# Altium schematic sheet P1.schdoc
size 297 x 209 mm; Symbol: Drawing-Symbol_A4; Company: 嘉立创EDA; Version: V1.0; Page Size: A4; @Project Name: 手机遥控开关; @Update Date: 2026-04-07; @Create Date: 2026-04-07; Device: Drawing-Symbol_A4; @Board Name: Board1; @Page Name: P1; @Create Time: 19:07:08; @Page Count: 1; @Page No: 1; @Schematic Name: Schematic1; @Update Time: 19:07:08; @Assembly Variant: Basic; Border: 1; Title Block Position: 3; Size: A4; Width: 1170; Height: 825; Region Start: 1; X Region Count: 6; Y Region Count: 4; Blade Width: 10
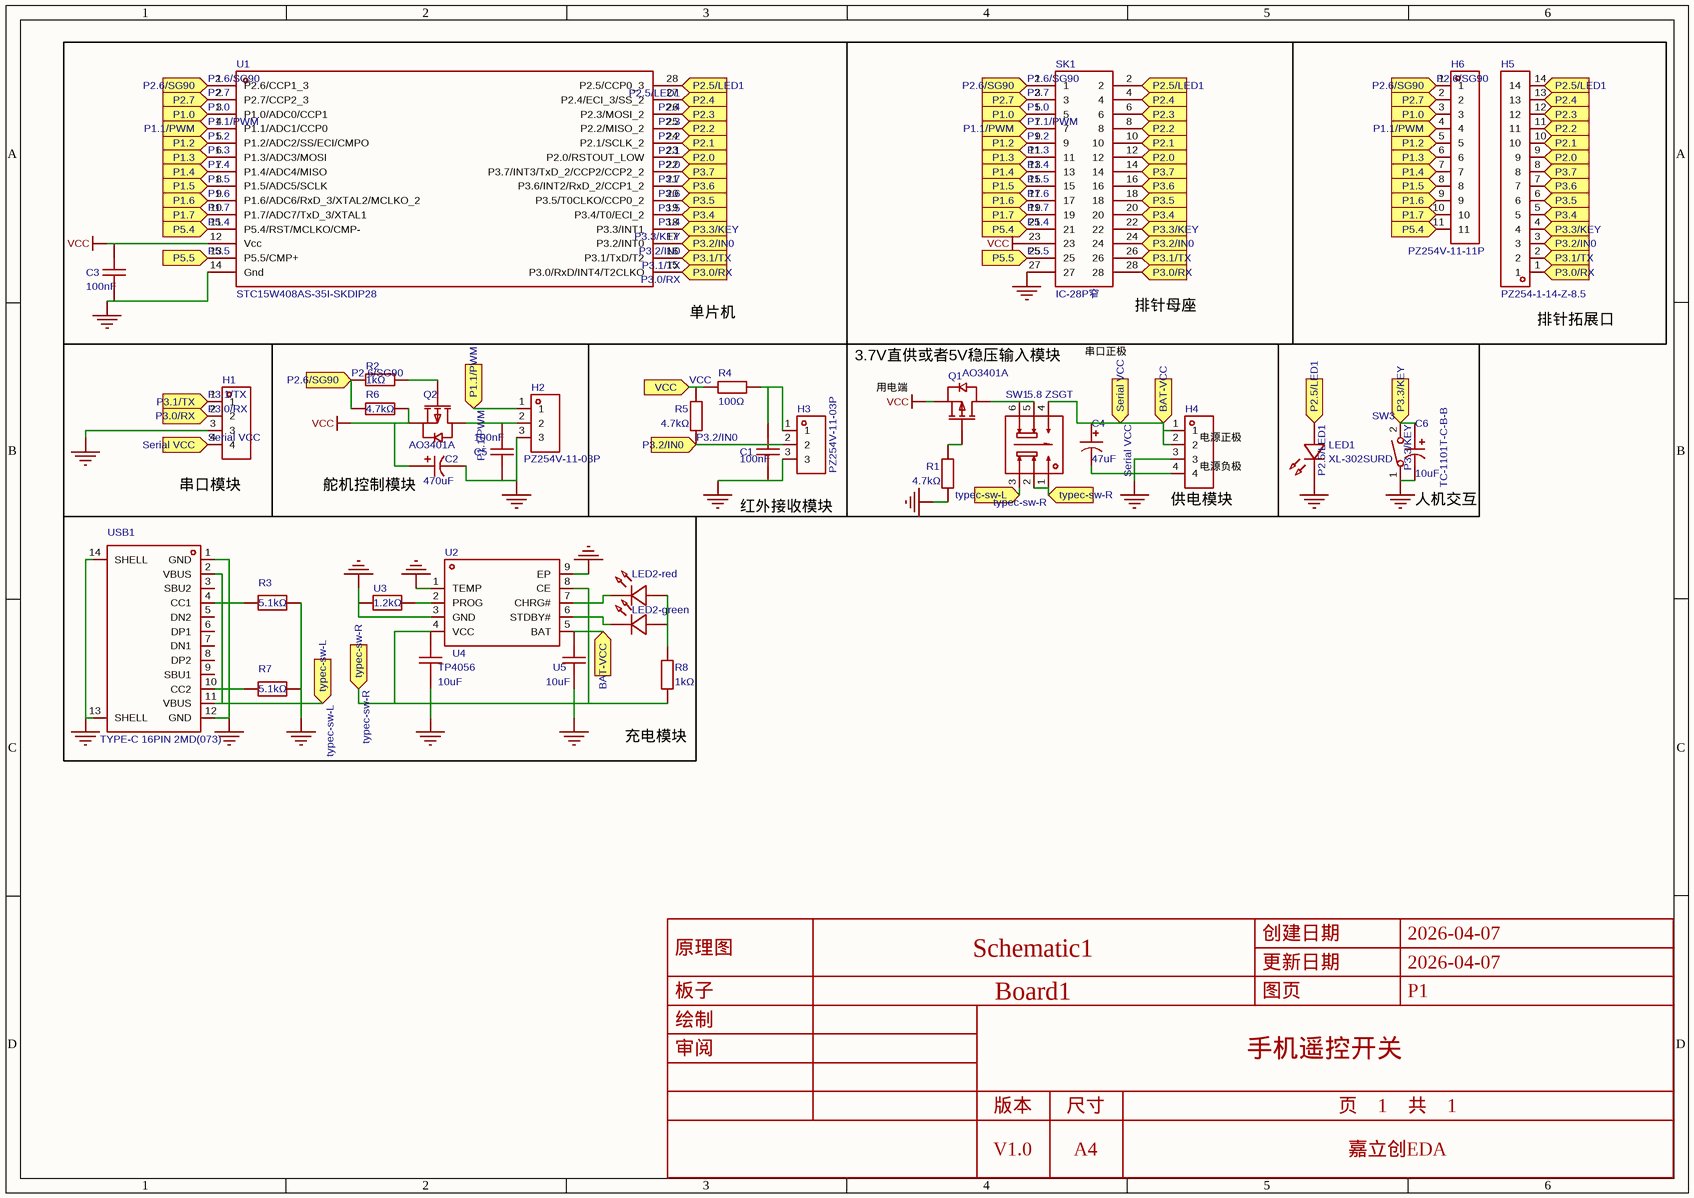
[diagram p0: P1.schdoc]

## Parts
C1  100nF  [CAP-TH_L5.0-W2.5-P5.00-D1.0]
C2  470uF  [CAP-TH_BD8.0-P3.50-D0.6-FD_1]
C3  100nF  [CAP-TH_L5.0-W2.5-P5.00-D1.0]
C4  47uF  [CAP-TH_BD6.3-P2.50-D1.0-FD]
C5  100nF  [CAP-TH_L5.0-W2.5-P5.00-D1.0]
C6  10uF  [CAP-TH_BD5.0-P2.00-D0.5-FD-A]
H1  (no value)  [HDR-TH_4P-P2.54-V-M]
H2  PZ254V-11-03P  [HDR-TH_3P-P2.54-V-M_PZ254V-11-03P]
H3  PZ254V-11-03P  [HDR-TH_3P-P2.54-V-M_PZ254V-11-03P]
H4  (no value)  [HDR-TH_4P-P2.54-V-M]
H5  PZ254-1-14-Z-8.5  [HDR-TH_14P-P2.54-V-M]
H6  PZ254V-11-11P  [HDR-TH_11P-P2.54-V-M]
LED1  XL-302SURD  [LED-TH_BD3.8-P2.54-RD]
LED2-green  (no value)  [LED-TH_BD3.8-P2.54-FD_GREEN]
LED2-red  (no value)  [LED-TH_BD3.8-P2.54-RD]
Q1  AO3401A  [SOT-23_L2.9-W1.3-P1.90-LS2.4-BR]
Q2  AO3401A  [SOT-23_L2.9-W1.3-P1.90-LS2.4-BR]
R1  4.7kΩ  [RES-TH_BD2.3-L6.5-P10.50-D0.5]
R2  1kΩ  [RES-TH_BD2.5-L6.5-P10.50-D0.6]
R3  5.1kΩ  [RES-TH_BD2.3-L6.5-P10.50-D0.5]
R4  100Ω  [RES-TH_BD2.2-L6.5-P10.50-D0.6]
R5  4.7kΩ  [RES-TH_BD2.3-L6.5-P10.50-D0.5]
R6  4.7kΩ  [RES-TH_BD2.3-L6.5-P10.50-D0.5]
R7  5.1kΩ  [RES-TH_BD2.3-L6.5-P10.50-D0.5]
R8  1kΩ  [RES-TH_BD2.5-L6.5-P10.50-D0.6]
SK1  IC-28P窄  [DIP-28_L36.0-W10.2-P2.54-LS10.2-BL]
SW1  5.8 ZSGT  [SW-TH_5.8ZSGT]
SW3  TC-1101T-C-B-B  [KEY-TH_2P-L6.0-W3.5-P6.50]
U1  STC15W408AS-35I-SKDIP28  [DIP-28_L35.0-W6.5-P2.54-LS7.6-BL]
U2  TP4056  [ESOP-8_L4.9-W3.9-P1.27-LS6.0-BL-EP]
U3  1.2kΩ  [RES-TH_BD2.4-L6.3-P10.30-D0.6]
U4  10uF  [CAP-TH_L5.5-W3.8-P5.08-D0.5]
U5  10uF  [CAP-TH_L5.5-W3.8-P5.08-D0.5]
USB1  TYPE-C 16PIN 2MD(073)  [USB-C-SMD_TYPE-C-6PIN-2MD-073]

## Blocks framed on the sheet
单片机: C3 U1
排针母座: SK1
排针拓展口: H5 H6
串口模块: H1
舵机控制模块: C2 C5 H2 Q2 R2 R6
红外接收模块: C1 H3 R4 R5
人机交互: C6 LED1 SW3
充电模块: LED2-green LED2-red R3 R7 R8 U2-U5 USB1

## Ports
BAT-VCC (in), P1.0 (in), P1.1/PWM (in), P1.2 (in), P1.3 (in), P1.4 (in), P1.5 (in), P1.6 (in), P1.7 (in), P2.0 (in), P2.1 (in), P2.2 (in), P2.3 (in), P2.4 (in), P2.5/LED1 (in), P2.6/SG90 (in), P2.7 (in), P3.0/RX (in), P3.1/TX (in), P3.2/IN0 (in), P3.3/KEY (in), P3.4 (in), P3.5 (in), P3.6 (in), P3.7 (in), P5.4 (in), P5.5 (in), Serial VCC (in), typec-sw-L (in), typec-sw-R (in), VCC (in)

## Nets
GND: C1.1 C2.2 C3.1 C4.2 C5.1 C6.2 H1.3 H2.3 H3.3 H4.3 H4.4 LED1.1(K) R1.1 R3.1 R3.2 R7.1 R7.2 SK1.27 SW3.1 U1.14(Gnd) U2.1(TEMP) U2.3(GND) U2.9(EP) U3.1 U4.1 U5.1 USB1.1(GND) USB1.4(CC1) USB1.10(CC2) USB1.12(GND) USB1.13(SHELL) USB1.14(SHELL)
VCC: C2.1 C3.2 Q1.2(S) Q2.2(S) R4.1 R5.2 R6.2 SK1.23 U1.12(Vcc) ; port VCC
P1.0: H6.3 SK1.5 U1.3(P1.0/ADC0/CCP1) ; port P1.0
P1.1/PWM: H2.1 H6.4 SK1.7 U1.4(P1.1/ADC1/CCP0) ; port P1.1/PWM
P1.2: H6.5 SK1.9 U1.5(P1.2/ADC2/SS/ECI/CMPO) ; port P1.2
P1.3: H6.6 SK1.11 U1.6(P1.3/ADC3/MOSI) ; port P1.3
P1.4: H6.7 SK1.13 U1.7(P1.4/ADC4/MISO) ; port P1.4
P1.5: H6.8 SK1.15 U1.8(P1.5/ADC5/SCLK) ; port P1.5
P1.6: H6.9 SK1.17 U1.9(P1.6/ADC6/RxD_3/XTAL2/MCLKO_2) ; port P1.6
P1.7: H6.10 SK1.19 U1.10(P1.7/ADC7/TxD_3/XTAL1) ; port P1.7
P2.0: H5.9 SK1.12 U1.23(P2.0/RSTOUT_LOW) ; port P2.0
P2.1: H5.10 SK1.10 U1.24(P2.1/SCLK_2) ; port P2.1
P2.2: H5.11 SK1.8 U1.25(P2.2/MISO_2) ; port P2.2
P2.3: H5.12 SK1.6 U1.26(P2.3/MOSI_2) ; port P2.3
P2.4: H5.13 SK1.4 U1.27(P2.4/ECI_3/SS_2) ; port P2.4
P2.5/LED1: H5.14 LED1.2(A) SK1.2 U1.28(P2.5/CCP0_3) ; port P2.5/LED1
P2.6/SG90: H6.1 R2.1 R6.1 SK1.1 U1.1(P2.6/CCP1_3) ; port P2.6/SG90
P2.7: H6.2 SK1.3 U1.2(P2.7/CCP2_3) ; port P2.7
P3.0/RX: H1.2 H5.1 SK1.28 U1.15(P3.0/RxD/INT4/T2CLKO) ; port P3.0/RX
P3.1/TX: H1.1 H5.2 SK1.26 U1.16(P3.1/TxD/T2) ; port P3.1/TX
P3.2/IN0: H3.2 H5.3 R5.1 SK1.24 U1.17(P3.2/INT0) ; port P3.2/IN0
P3.3/KEY: C6.1 H5.4 SK1.22 SW3.2 U1.18(P3.3/INT1) ; port P3.3/KEY
P3.4: H5.5 SK1.20 U1.19(P3.4/T0/ECI_2) ; port P3.4
P3.5: H5.6 SK1.18 U1.20(P3.5/T0CLKO/CCP0_2) ; port P3.5
P3.6: H5.7 SK1.16 U1.21(P3.6/INT2/RxD_2/CCP1_2) ; port P3.6
P3.7: H5.8 SK1.14 U1.22(P3.7/INT3/TxD_2/CCP2/CCP2_2) ; port P3.7
P5.4: H6.11 SK1.21 U1.11(P5.4/RST/MCLKO/CMP-) ; port P5.4
P5.5: SK1.25 U1.13(P5.5/CMP+) ; port P5.5
Serial VCC: C4.1 H1.4 H4.1 H4.2 SW1.4 U2.5(BAT) U5.2 ; port Serial VCC, port BAT-VCC
typec-sw-L: SW1.3 USB1.2(VBUS) USB1.11(VBUS) ; port typec-sw-L
typec-sw-R: R8.2 SW1.1 SW1.2 U2.4(VCC) U2.8(CE) U4.2 ; port typec-sw-R
NetC1_2: C1.2 H3.1 R4.2
NetC5_2: C5.2 H2.2 Q2.3(D)
NetLED2-green_1: LED2-green.1(A) LED2-red.2(A) R8.1
NetLED2-green_2: LED2-green.2(K) U2.6(STDBY#)
NetLED2-red_1: LED2-red.1(K) U2.7(CHRG#)
NetQ1_1: Q1.1(G) R1.2
NetQ1_3: Q1.3(D) SW1.5 SW1.6
NetQ2_1: Q2.1(G) R2.2
NetU2_2: U2.2(PROG) U3.2

Not connected (* = marked no-connect by the designer): USB1 3(SBU2) 5(DN2) 6(DP1) 7(DN1) 8(DP2) 9(SBU1)

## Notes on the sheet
- (near Q1) 3.7V直供或者5V稳压输入模块
- 串口正极
- 用电端
- (near H4) 供电模块
- (near H4) 电源正极
- (near H4) 电源负极

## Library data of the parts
C1 = CC1H104MC1FD3F6C10MF: 容值:100nF;精度:±20%;额定电压:50V;温度系数:Y5V;; Manufacturer: Dersonic(德尔创); AddInBom: yes; ModelId: 08e3d7481fc7486bb1b263873f51e1e10819f05c4eef4c71ace90d822a990e87; ModelName: CAP-TH_BD5.0-W2.5-P5.08; ModelTransform: 224.652,98.425,0,0,0,0,-0.005,0,-137.795; Tolerance: ±20%; Voltage Rating: 50V; Pin Spacing: 5.08mm; Temperature Coefficient: Y5V; Body Thickness: 2.2mm
C2 = CD2884771EM0812VFL: 容值:470uF;精度:±20%;额定电压:25V;纹波电流:905mA@100kHz;等效串联电阻(ESR):69mΩ@100kHz;; Manufacturer: HRK(鸿瑞凯电子); AddInBom: yes; ModelId: 5fc21599cab34df2ad7753b19b2f52860819f05c4eef4c71ace90d822a990e87; ModelTransform: 315.365,314.914,0,0,0,0,0,0,-196.85; Tolerance: ±20%; Voltage Rating: 25V; Pin Spacing: 3.5mm; Lifetime: 3000hrs@105℃
C3 C5 = CC1H104MC1FD3F6C10MF: 容值:100nF;精度:±20%;额定电压:50V;温度系数:Y5V;; Manufacturer: Dersonic(德尔创); 3D Model: 08e3d7481fc7486bb1b263873f51e1e10819f05c4eef4c71ace90d822a990e87; 3D Model Transform: 224.652,98.425,0,0,0,0,-0.005,0,-137.795; Tolerance: ±20%; Voltage Rating: 50V; Pin Spacing: 5.08mm; Temperature Coefficient: Y5V; Body Thickness: 2.2mm; AddInBom: yes; ModelName: CAP-TH_BD5.0-W2.5-P5.08
C4 = ERS1HM470E110T: 容值:47uF;精度:±20%;额定电压:50V;; Manufacturer: AISHI(艾华集团); AddInBom: yes; ModelId: 0a4db4bf24b443b3be4905be97ff10c50819f05c4eef4c71ace90d822a990e87; ModelTransform: 248.4247,247.99777,0,0,0,0,0,0,-137.795; Tolerance: ±20%; Voltage Rating: 50V; Pin Spacing: 2.5mm; Lifetime: 5000hrs@105℃
C6 = ERG50V10M5X11: 容值:10uF;精度:±20%;额定电压:50V;纹波电流:180mA@100kHz;等效串联电阻(ESR):1.3Ω@100kHz;; Manufacturer: JIERR(捷而瑞); AddInBom: yes; ModelId: 230b3bd6484f4b52b9cf74c8bd6c61990819f05c4eef4c71ace90d822a990e87; ModelTransform: 197.2437,197.23953,0,0,0,0,0,0,-196.85; Tolerance: ±20%; Voltage Rating: 50V; Pin Spacing: 2mm; Lifetime: 2000hrs@105℃
H1 H4 = PZ254V-11-04P: 插针结构:1x4P;间距:2.54mm;行距:-;圆针/方针:方针;安装方式:直插;排数:单排;总PIN位数:4P;额定电流:3A;额定电压:250V;配合针长度:6mm;塑高:2.5mm;端接针长度:3mm;触头材质:-;工作温度:-40℃~+105℃;颜色:黑色;; Manufacturer: XFCN(兴飞); Symbol: PZ254V-11-04P_C2691448; AddInBom: yes; ModelId: 112f4d05e8d64e99ab9a333894bea4f90819f05c4eef4c71ace90d822a990e87; ModelName: HDR-TH_4P-P2.54-M-LI-1X4P; ModelTransform: 399.999,104.7242,0,0,0,0,0,0,-118.11; Pin Structure: 1x4P; Pitch: 2.54mm; Circluar Pins/Square Pins: 方针; Current Rating: 3A; Voltage Rating (Max): 250V
H2 H3 = PZ254V-11-03P: 插针结构:1x3P;间距:2.54mm;行距:-;圆针/方针:方针;安装方式:直插;排数:单排;总PIN位数:3P;额定电流:3A;额定电压:250V;配合针长度:6mm;塑高:2.5mm;端接针长度:3mm;工作温度:-40℃~+105℃;颜色:黑色;; Manufacturer: XFCN(兴飞); Symbol: PZ254V-11-03P_C2937625; AddInBom: yes; ModelId: bd28a638fbd247be9398fd5d39c366ec0819f05c4eef4c71ace90d822a990e87; ModelTransform: 300.3931,100,0,0,0,0,0,0,-118.11; Pin Structure: 1x3P; Pitch: 2.54mm; Circluar Pins/Square Pins: 方针; Current Rating: 3A; Voltage Rating (Max): 250V
H5 = PZ254-1-14-Z-8.5: 插针结构:1x14P;间距:2.54mm;行距:-;圆针/方针:方针;安装方式:直插;排数:单排;总PIN位数:14P;额定电流:3A;额定电压:-;配合针长度:6mm;塑高:2.5mm;端接针长度:3mm;触头材质:黄铜;工作温度:-40℃~+105℃;颜色:黑色;; Manufacturer: HCTL(华灿天禄); AddInBom: yes; ModelId: 08b06314cd6a40fe8bae6f2b80f3ecbb0819f05c4eef4c71ace90d822a990e87; ModelName: HDR-TH_14P-P2.54-M-LI-1X14P; ModelTransform: 1400.001,98.425,0,0,0,0,0,0,-118.11; Pin Structure: 1x14P; Pitch: 2.54mm; Circluar Pins/Square Pins: 方针; Current Rating: 3A
H6 = PZ254V-11-11P: 插针结构:1x11P;间距:2.54mm;行距:-;圆针/方针:方针;安装方式:直插;排数:单排;总PIN位数:11P;额定电流:3A;额定电压:250V;配合针长度:6mm;塑高:2.5mm;端接针长度:3mm;触头材质:-;工作温度:-40℃~+105℃;颜色:黑色;; Manufacturer: XFCN(兴飞); AddInBom: yes; ModelId: 3161e11271394836bba9184bfd8f20d70819f05c4eef4c71ace90d822a990e87; ModelName: HDR-TH_11P-P2.54-M-LI-1X11P; ModelTransform: 1099.99772,98.425,0,0,0,0,0,0,-118.11; Pin Structure: 1x11P; Pitch: 2.54mm; Circluar Pins/Square Pins: 方针; Current Rating: 3A; Voltage Rating (Max): 250V
LED1 = XL-302SURD: 灯头类型:3mm圆形灯头;发光颜色:红色;正向压降(Vf):2.2V;功率:50mW;正向电流:20mA;波长:620nm~630nm;二极管配置:-;透镜颜色:红色透镜;色温:-;发光强度:1cd;发光角度:35°;载带方式:-;工作温度:-20℃~+85℃;; Manufacturer: XINGLIGHT(成兴光); AddInBom: yes; ModelId: 2442e7b519d8425caacaaf67354e0cb90819f05c4eef4c71ace90d822a990e87; ModelTransform: 134.372,149.6,0,180,0,0,6.89,0,-196.85; Illumination Color: 红色; Voltage - Forward(Vf): 2.2V; Power(Watts): 50mW; Forward Current: 20mA; Peak Wavelength: 625nm; Lens Color: 红色透镜; Luminous Intensity: 1cd; Viewing Angle: 35°
LED2-green = XL-302UGD: 灯头类型:3mm圆形灯头;发光颜色:翠绿色;正向压降(Vf):3.6V;功率:70mW;正向电流:20mA;波长:520nm~530nm;二极管配置:-;透镜颜色:绿色透镜;色温:-;发光强度:3cd;发光角度:30°;载带方式:-;工作温度:-20℃~+85℃;; Manufacturer: XINGLIGHT(成兴光); AddInBom: yes; ModelId: c917953ee2724e1d8eea37a428b0e1190819f05c4eef4c71ace90d822a990e87; ModelTransform: 134.40603,149.41647,0,0,0,0,-7.874,0,-137.795; Illumination Color: 翠绿色; Voltage - Forward(Vf): 3.6V; Power(Watts): 70mW; Forward Current: 20mA; Peak Wavelength: 520nm; Lens Color: 绿色透镜; Luminous Intensity: 3cd; Viewing Angle: 30°
LED2-red = XL-302SURD: 灯头类型:3mm圆形灯头;发光颜色:红色;正向压降(Vf):2.2V;功率:50mW;正向电流:20mA;波长:620nm~630nm;二极管配置:-;透镜颜色:红色透镜;色温:-;发光强度:1cd;发光角度:35°;载带方式:-;工作温度:-20℃~+85℃;; Manufacturer: XINGLIGHT(成兴光); 3D Model: 2442e7b519d8425caacaaf67354e0cb90819f05c4eef4c71ace90d822a990e87; 3D Model Transform: 134.372,149.6,0,180,0,0,6.89,0,-196.85; Illumination Color: 红色; Voltage - Forward(Vf): 2.2V; Power(Watts): 50mW; Forward Current: 20mA; Peak Wavelength: 625nm; Lens Color: 红色透镜; Luminous Intensity: 1cd; Viewing Angle: 35°; AddInBom: yes
Q1 = AO3401A_C15127: 数量:1个P沟道;漏源电压(Vdss):30V;连续漏极电流(Id):4A;导通电阻(RDS(on)):47mΩ@10V；85mΩ@2.5V；60mΩ@4.5V;耗散功率(Pd):-;阈值电压(Vgs(th)):900mV;; Manufacturer: AOS; 3D Model: c62791f0466c4ae2a892c056b845b0ca0819f05c4eef4c71ace90d822a990e87; 3D Model Transform: 98.64468,114.173,0,180,0,0,0.001,-0.002,0; Number: 1个P沟道; Drain to Source Voltage: 30V; Current - Continuous Drain(Id): 4A; Gate Threshold Voltage (Vgs(th)): 900mV; Gate Charge(Qg): 14nC@10V; Input Capacitance(Ciss): 645pF; Reverse Transfer Capacitance (Crss@Vds): 55pF; Output Capacitance(Coss): 80pF; AddInBom: yes; ModelName: SOT-23-3P_L2.9-W1.3-H1.0-LS2.4-P0.95
Q2 = AO3401A_C15127: 数量:1个P沟道;漏源电压(Vdss):30V;连续漏极电流(Id):4A;导通电阻(RDS(on)):47mΩ@10V；85mΩ@2.5V；60mΩ@4.5V;耗散功率(Pd):-;阈值电压(Vgs(th)):900mV;; Manufacturer: AOS; AddInBom: yes; ModelId: c62791f0466c4ae2a892c056b845b0ca0819f05c4eef4c71ace90d822a990e87; ModelName: SOT-23-3P_L2.9-W1.3-H1.0-LS2.4-P0.95; ModelTransform: 98.64468,114.173,0,180,0,0,0.001,-0.002,0; Number: 1个P沟道; Drain to Source Voltage: 30V; Current - Continuous Drain(Id): 4A; Gate Threshold Voltage (Vgs(th)): 900mV; Gate Charge(Qg): 14nC@10V; Input Capacitance(Ciss): 645pF; Reverse Transfer Capacitance (Crss@Vds): 55pF; Output Capacitance(Coss): 80pF
R1 R5 R6 = MF1/4W-4.7KΩ±1% T: 电阻类型:金属膜电阻;阻值:4.7kΩ;精度:±1%;功率:250mW;温度系数:±100ppm/℃;; Manufacturer: CCO(千志电子); Symbol: MF1/4W-4.7KΩ±1% T52; AddInBom: yes; ModelId: 8e6c7ee8323443d1ab8f0504b6353c8c0819f05c4eef4c71ace90d822a990e87; ModelName: RES-TH_D2.3-L6.5-P10.50; ModelTransform: 431.1015,91.3384,0,0,0,0,0.197,0,-137.795; Tolerance: ±1%; Voltage-Supply(Max): 250V; Power(Watts): 250mW
R2 = MFR0W4F1001A50: 电阻类型:金属膜电阻;阻值:1kΩ;精度:±1%;功率:250mW;温度系数:±50ppm/℃;; Manufacturer: UNI-ROYAL(厚声); AddInBom: yes; ModelId: 8e6c7ee8323443d1ab8f0504b6353c8c0819f05c4eef4c71ace90d822a990e87; ModelName: RES-TH_D2.3-L6.5-P10.50; ModelTransform: 431.1015,91.3384,0,0,0,0,0.197,0,-137.795; Tolerance: ±1%; Voltage-Supply(Max): 250V; Power(Watts): 250mW
R3 R7 = MF1/4W-5.1KΩ±1%T52: 电阻类型:金属膜电阻;阻值:5.1kΩ;精度:±1%;功率:250mW;温度系数:±200ppm/℃;; Manufacturer: 华星机电; AddInBom: yes; ModelId: 8e6c7ee8323443d1ab8f0504b6353c8c0819f05c4eef4c71ace90d822a990e87; ModelName: RES-TH_D2.3-L6.5-P10.50; ModelTransform: 431.1015,91.3384,0,0,0,0,0.197,0,-137.795; Tolerance: ±1%; Power(Watts): 250mW
R4 = MFR0W4F1000A50: 电阻类型:金属膜电阻;阻值:100Ω;精度:±1%;功率:250mW;温度系数:±50ppm/℃;; Manufacturer: UNI-ROYAL(厚声); AddInBom: yes; ModelId: 259c3103781c424fb695c8049f0a17f30819f05c4eef4c71ace90d822a990e87; ModelTransform: 437.007,91.18383,0,0,0,0,0,0,-137.795; Tolerance: ±1%; Voltage-Supply(Max): 250V; Power(Watts): 250mW
R8 = MFR0W4F1001A50: 电阻类型:金属膜电阻;阻值:1kΩ;精度:±1%;功率:250mW;温度系数:±50ppm/℃;; Manufacturer: UNI-ROYAL(厚声); 3D Model: 8e6c7ee8323443d1ab8f0504b6353c8c0819f05c4eef4c71ace90d822a990e87; 3D Model Transform: 431.1015,91.3384,0,0,0,0,0.197,0,-137.795; Tolerance: ±1%; Voltage-Supply(Max): 250V; Power(Watts): 250mW; AddInBom: yes; ModelName: RES-TH_D2.3-L6.5-P10.50
SK1 = IC-28P窄: 适配封装类型:DIP;间距:2.54mm;行距:7.62mm;圆孔/方孔:方孔;总PIN数:28P;触头材质:铜合金;触头镀层:锡;; Manufacturer: BOOMELE(博穆精密); Symbol: IC seat; AddInBom: yes; ModelId: c432ac7ca1d34f1eade8f37969cec3990819f05c4eef4c71ace90d822a990e87; ModelName: DIP-28_L36.0-W10.2-H5.0-P2.54-LS10.2-BL; ModelTransform: 1399.997,399.999,0,0,0,0,-0.039,0,-137.795; Adaptation Package Type: DIP; Pitch: 2.54mm; Row Spacing: 7.62mm; Circular Holes/Square Holes: 方孔; Number of Positions: 28P
SW1 = 5.8 ZSGT: 电路结构:双刀双掷;自锁/无锁:自锁;安装方式:直插;触点电流:110mA;额定电压:30V;带灯:不带;作用力:1.5N;工作寿命:10万次;; Manufacturer: SHOU HAN(首韩); AddInBom: yes; ModelId: 3b6e980975cd43bda015b2e9aaa869d30819f05c4eef4c71ace90d822a990e87; ModelTransform: 228.346,228.346,0,0,0,0,0,0,-141.732; Circuit: 双刀双掷; Self Lock / No Lock: 自锁; Actuator Style: 方形按钮; Contact Current: 110mA; Voltage Rating: 30V; Actuator/Cap Color: 白色; With Lamp: 不带; Operating Force: 1.5N; Life: 10万次
SW3 = TC-1101T-C-B-B: 电路结构:单刀单掷;按钮形状:矩形按钮;作用力:2.6N;安装方式:直插;开关长度:6mm;开关宽度:3.5mm;开关高度:5mm;带支架:不带支架;触点电流:50mA;额定电压:12V;带灯:无;工作寿命:5万次;; Manufacturer: XKB Connection(中国星坤); AddInBom: yes; ModelId: 0815bb095c804560995555b82a2293fb0819f05c4eef4c71ace90d822a990e87; ModelName: KEY-TH_2P-L6.0-W3.5-H5.0-LS7.9-P6.50; ModelTransform: 310.81938,137.795,0,0,0,0,0,0,-137.795; Circuit: 单刀单掷; Actuator Style: 矩形按钮; Operating Force: 2.6N; Switch Height: 5mm; with Bracket: 不带支架; Contact Current: 50mA; Voltage Rating: 12V; Actuator/Cap Color: 黑色; With Lamp: 无; Life: 5万次
U1 = STC15W408AS-35I-SKDIP28: CPU内核:51家族;; Manufacturer: STC; AddInBom: yes; ModelId: 451206f16f5b42719917771906ab43c40819f05c4eef4c71ace90d822a990e87; ModelTransform: 1362.20208,307.8734,0,0,0,0,0,0,-118.11; CPU Core: 51家族; Program Storage Size: 8KB; Program Memory Type: FLASH; Number of I/O: 26; ADC (Bit): 10bit; Voltage - Supply: 2.5V~5.5V
U2 = TP4056_C725790: 工作电压:4V~6.5V;最大充电电流:1A;电池类型:锂电池;电池节数:1;; Manufacturer: UMW(友台半导体); AddInBom: yes; ModelId: d3e00daa36c445139c055a3b9efb85d20819f05c4eef4c71ace90d822a990e87; ModelName: ESOP-8_L4.9-W3.9-H1.6-LS6.0-P1.27; ModelTransform: 240.157,192.913,0,90,0,0,0,0,0; The Chip Type: 充电芯片; Charge Current - Max: 1A; Charging Saturation Voltage: 4.2V; Type of Battery: 锂电池; Number of Cells: 1; Battery Temperature Detection: 支持; Supply Current (Iq): 35uA
U3 = MFR-25FBF52-1K2: 电阻类型:金属膜电阻;阻值:1.2kΩ;精度:±1%;功率:250mW;温度系数:±100ppm/℃;; Manufacturer: YAGEO(国巨); AddInBom: yes; ModelId: 463263665006444ab7a47bd11b0cf9560819f05c4eef4c71ace90d822a990e87; ModelTransform: 427.165,94.32816,0,0,0,0,0,0,-196.85; Tolerance: ±1%; Power(Watts): 250mW
U4 U5 = CD1H106KC9IER2F100: 容值:10uF;精度:±10%;额定电压:50V;温度系数:X5R;; Manufacturer: Dersonic(德尔创); AddInBom: yes; ModelId: 30ed28be0b3b4d15a702e5d47761fb1d0819f05c4eef4c71ace90d822a990e87; ModelName: CAP-TH_L4.2-W3.8-H3.8-P5.08; ModelTransform: 215.7476,118.11,0,0,0,0,0,0,-137.795; Tolerance: ±10%; Voltage Rating: 50V; Temperature Coefficient: X5R; Pin Spacing: 5.08mm
USB1 = TYPE-C 16PIN 2MD(073): 连接器类型:Type-C;协议标准:-;公母:母;安装方式:卧贴;触点数量:16P;端口数量:1;额定电流 - 电源:3A;工作温度:-25℃~+85℃;; Manufacturer: SHOU HAN(首韩); AddInBom: yes; ModelId: 3a41b9ec9b654a0fad4d118405ec62900819f05c4eef4c71ace90d822a990e87; ModelTransform: 351.9678,298.4246,0,0,0,0,0,-47.244,-35.433; Gender: 母; Number of Contacts: 16P; Number of Ports: 1; Current Rating-Power: 3A; Voltage Rating: 5V; Connect-Disconnect Life: 1万次; Detection color: 黑色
